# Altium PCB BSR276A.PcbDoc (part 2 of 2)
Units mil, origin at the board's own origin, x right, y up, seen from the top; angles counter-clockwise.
Board outline 2517.71 x 2251 mil, 4 copper layers (Top Layer, Signal Layer 1, Signal Layer 2, Bottom Layer), stack 61.6 mil thick; 70 components, 21 nets, 118 pads, 66 vias.
Unrouted connection lines stored in the file: 1.
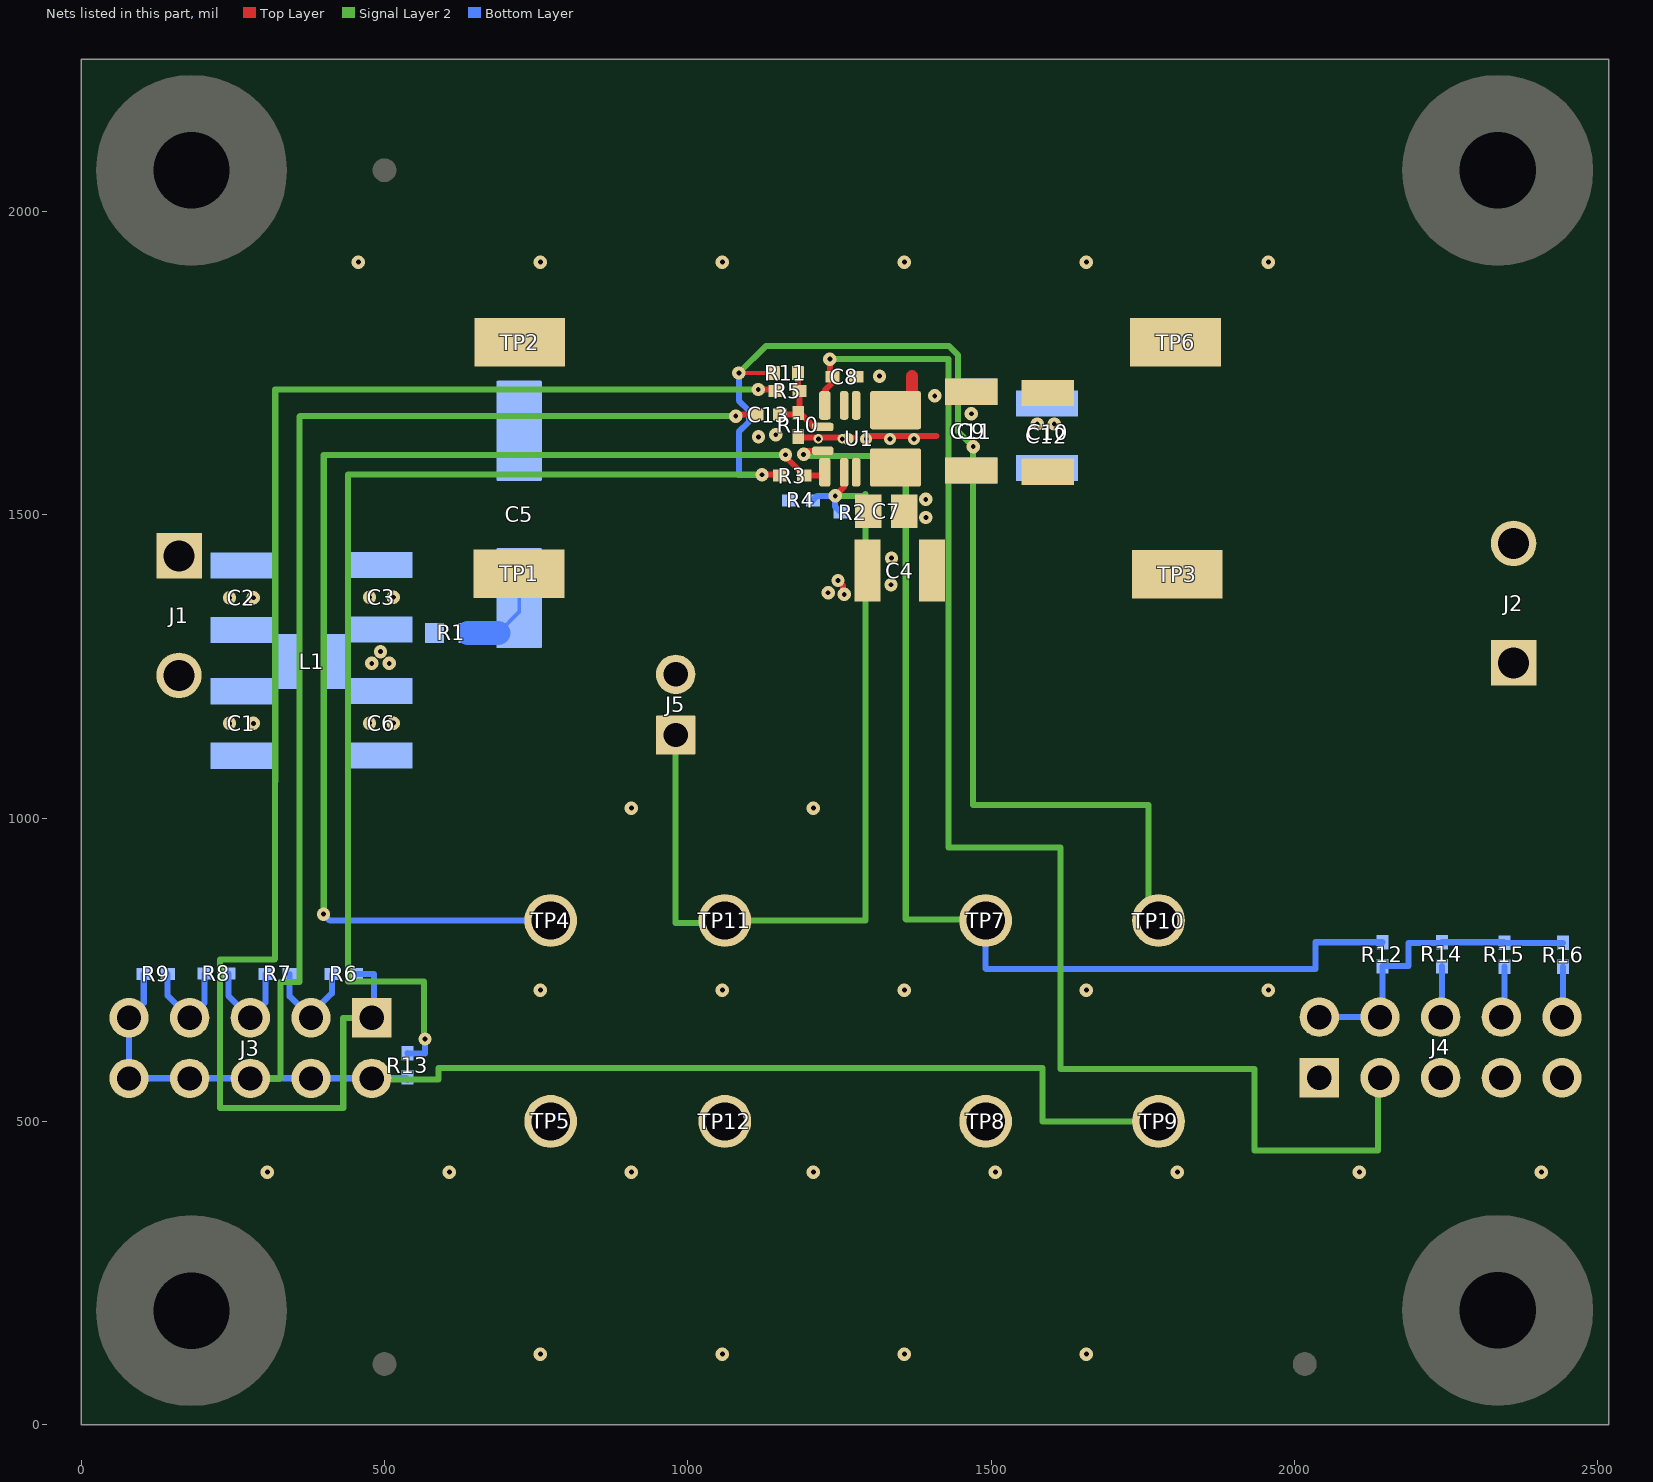
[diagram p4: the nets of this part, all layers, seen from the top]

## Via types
v1: diameter 22, hole 8, Top Layer to Bottom Layer, tented both sides, 61 vias
v2: diameter 19.68, hole 7.87, Top Layer to Bottom Layer, tented both sides, 3 vias
v3: diameter 15.75, hole 7.87, Top Layer to Bottom Layer, tented both sides, 2 vias

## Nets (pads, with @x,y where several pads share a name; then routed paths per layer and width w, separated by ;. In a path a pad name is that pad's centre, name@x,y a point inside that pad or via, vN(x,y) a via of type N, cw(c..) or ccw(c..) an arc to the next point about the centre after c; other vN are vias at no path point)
1.8Vout: J3.1 R5.1 R6.2 | length 2604.8
  Top Layer w10: v1(1116.14,1706.25) 1139.51,1706.25 1143.01,1702.76 1144.34,1704.09 R5.1@1144.69,1703.74
  Signal Layer 2 w10: J3.1@479,670.87 478.24,670.11 432.17,670.11 432.17,521.7 228.97,521.7 228.97,766.73 319,766.73 319.98,767.72 319.98,1060.04 320,1706.25 v1(1116.14,1706.25)
  Bottom Layer w10: R6.2@452.69,743.11 483.02,743.11 483.02,674.88 J3.1@479,670.87
2.5Vout: J3.3 R6.1 R7.2 | length 173.3
  Bottom Layer w10: R7.2@343.69,743.11 343.69,706.18 J3.3@379,670.87 379,676.65 413.32,710.96 R6.1@413.32,743.11
3.3Vout: J3.5 R7.1 R8.2 | length 171
  Bottom Layer w10: R8.2@242.69,744.09 242.69,707.18 J3.5@279,670.87 304.32,696.18 R7.1@304.32,743.11
5Vout: J3.7 R8.1 R9.2 | length 170.6
  Bottom Layer w10: R9.2@142.69,743.11 142.69,707.18 J3.7@179,670.87 203.32,695.18 R8.1@203.32,744.09
12Vout: C13.1 J3.2 J3.4 J3.6 J3.8 J3.9 J3.10 R9.1 R13.1 TP9.1 | length 3972.9
  Top Layer w10: v1(1079,1662.4) 1081.95,1665.35 C13.1@1112.8,1665.35
  Signal Layer 2 w10: J3.6@279,570.87 279.24,570.62 328.57,570.62 328.57,729.9 360,729.9 360,1661.4 361,1662.4 v1(1079,1662.4) ; J3.2@479,570.87 480.81,569.05 589.06,569.05 589.06,587.66 1584.92,587.66 1584.92,500 TP9.1@1776,500
  Bottom Layer w10: J3.10@79,570.87 J3.10@79,571.06 ; R9.1@103.32,743.11 103.32,695.18 J3.9@79,670.87 J3.10@79,571.06 ; R13.1@538.39,568.99 536.31,571.06 J3.10@79,571.06
GND: C1.2 C2.2 C3.2 C4.2 C5.1 C6.2 C7.2 C8.1 C9.2 C10.2 C11.2 C12.2 J1.1 J2.2 J4.1 J4.5 J4.7 J4.9 J5.2 R4.2 R10.1 TP2.1 TP5.1 TP6.1 TP8.1 TP12.1 U1.10 | length 207.7
  Top Layer w10: R10.1@1182.09,1628.36 1182.09,1626.89 U1.10@1272.64,1626.89 ; v2@1294,1629.69 1409.68,1629.69
  other v1: 757,116.39 1057,116.39 1357,116.39 1657,116.39 307,416.39 607,416.39 907,416.39 1207,416.39 1507,416.39 1807,416.39 2107,416.39 2407,416.39 757,716.39 1057,716.39 1357,716.39 1657,716.39 1957,716.39 907,1016.39 1207,1016.39 244.55,1156 283.92,1156 475.32,1156.38 514.68,1156.38 244.55,1363 283.92,1363 475.32,1364.01 514.68,1364.01 1334.92,1384.53 1335.84,1428.45 1392.41,1495.44 1392.25,1525.27 1116.64,1628.27 1145.12,1631.7 1576,1649.61 1604,1649.61 1467.52,1666.34 1407.21,1695.87 1315.95,1728.46 457,1916.39 757,1916.39 1057,1916.39 1357,1916.39 1657,1916.39 1957,1916.39
  other v2: 1294.09,1625 1333.46,1625 1372.83,1625
  other v3: 1215.35,1625 1254.72,1625
NetC5_2: C5.2 R1.1 | length 121.6
  Bottom Layer w6: C5.2@687.6,1305.13 722,1339.54 C5.2@722,1362.56
  Bottom Layer w40: R1.1@637.63,1305.13 C5.2@687.6,1305.13
NetJ4_2: J4.2 J4.4 R12.1 R14.2 R15.2 R16.2 | length 523.5
  Bottom Layer w10: J4.2@2041,671.85 J4.4@2141,671.85 2145,675.85 R12.1@2145,755.91 2188.03,755.91 2188.03,794.31 2242.03,794.31 R14.2@2243,795.28 2345.02,795.28 R15.2@2346,794.29 R16.2@2443,794.29 ; J4.4@2157.18,669.39 J4.4@2157.57,668.99
NetJ4_6: J4.6 R14.1 | length 91.4
  Bottom Layer w10: J4.6@2241,671.85 2243,673.85 R14.1@2243,755.91 ; J4.6@2254.92,671.65 2257.57,668.99 J4.6@2259.54,670.96
NetJ4_8: J4.8 R15.1 | length 85.1
  Bottom Layer w10: J4.8@2341,671.85 2346,676.85 R15.1@2346,754.92
NetJ4_10: J4.10 R16.1 | length 90.7
  Bottom Layer w10: J4.10@2441,671.85 2443,673.85 R16.1@2443,754.92 ; J4.10@2452.76,673.81 J4.10@2457.57,668.99
Vboot: U1.7
VCC: C8.2 J4.3 U1.8 | length 2409.2
  Top Layer w10: U1.8@1225.91,1680.12 1225.91,1704.83 1238.6,1717.52 C8.2@1238.6,1727.36 ; C8.2@1234.25,1733.27 v1(1234.25,1756.44)
  Signal Layer 2 w10: v1@1237.66,1759.84 v1(1234.25,1756.44) 1429.56,1756.44 1429.56,951.34 1614.61,951.34 1614.61,586.61 1934.41,586.61 1934.41,452.19 2137.61,452.19 2137.61,568.46 J4.3@2141,571.85
Ven: J5.1 R2.1 R4.1 TP11.1 U1.2 | length 1505.3
  Top Layer w10: v1@1245.57,1531 v1(1243,1531) 1257.87,1545.87 U1.2@1257.87,1569.88
  Signal Layer 2 w10: J5.1@980,1136.81 980,826.82 1056.82,826.82 TP11.1@1060.86,830.86 ; TP11.1@1061,831 TP11.1@1060.86,830.86 ; v1(1243,1531) 1289.86,1531 1293.31,1534.45 1293.31,830.86 TP11.1@1060.86,830.86
  Bottom Layer w10: TP11.1@1050.2,843.5 TP11.1@1054.82,838.88 ; R4.1@1206.31,1523.62 1213.69,1531 v1(1243,1531) 1243,1513.26 R2.1@1252.32,1503.94
Vfb: C13.2 R5.2 R10.2 R11.1 U1.9 | length 137.2
  Top Layer w6: R5.2@1181.42,1706.38 R5.2@1184.06,1703.74
  Top Layer w10: C13.2@1152.17,1664.86 1179.22,1664.86 R10.2@1182.09,1667.73 ; R5.2@1181.42,1706.38 R11.1@1181.42,1733.52 ; R5.2@1184.06,1703.74 1184.06,1669.7 R10.2@1182.09,1667.73 ; U1.9@1211.4,1645.75 1206.61,1645.75 1184.63,1667.73 R10.2@1182.09,1667.73
VIN: C3.1 C4.1 C6.1 C7.1 L1.2 R1.2 R2.2 TP1.1 U1.3 | length 27.3
  Top Layer w10: v1(1247.53,1391.55) 1255.58,1383.51 1255.58,1370.88 v1(1257.87,1368.59)
  other v1: 479,1254.92 507.87,1254.92 493.64,1274.33 1231.32,1371.26
VIN_EMI: C1.1 C2.1 J1.2 L1.1
VOUT: C9.1 C10.1 C11.1 C12.1 J2.1 R3.1 R11.2 R13.2 TP3.1 TP10.1 U1.4 | length 3723.9
  Top Layer w6: v1(1084.32,1733.52) R11.2@1142.05,1733.52
  Top Layer w10: v1(1122.32,1565.94) 1151.18,1565.94 R3.1@1152.56,1564.57
  Signal Layer 2 w10: v1(567,635.83) 565,637.83 565,730.33 440,730.33 440,1565.94 v1(1122.32,1565.94) ; v1(1084.32,1733.52) 1129.14,1778.34 1430.15,1778.34 1445.61,1762.88 1445.61,1637.06 v1(1470.47,1612.2) 1470.47,1021.16 1759.53,1021.16 1759.53,847.47 TP10.1@1776,831
  Bottom Layer w10: R13.2@538.39,612.3 538.46,612.22 567,612.22 v1(567,635.83) ; v1(1084.32,1733.52) 1084.32,1688.06 1100.91,1671.48 1100.91,1653.33 1084.32,1636.74 1084.32,1565.09 1121.46,1565.09 v1(1122.32,1565.94)
Vpgood: R3.2 TP4.1 U1.1 | length 1988.8
  Top Layer w10: v1(1161.1,1598.74) 1161.1,1595.4 R3.2@1191.93,1564.57 1220.59,1564.57 U1.1@1225.91,1569.88
  Signal Layer 2 w10: v1(399.54,841.54) 400,842 400,1598.74 v1(1161.1,1598.74)
  Bottom Layer w10: v1(399.54,841.54) 410.07,831 TP4.1@774,831 ; TP4.1@774.61,842.52 TP4.1@780.51,848.43
Vrt: R12.2 TP7.1 U1.11 | length 1876.4
  Top Layer w10: v1(1191.06,1599.49) 1196.89,1605.32 U1.11@1222.44,1605.32
  Signal Layer 2 w10: v1(1191.06,1599.49) 1193.62,1596.93 1359.35,1596.93 1359.35,833.33 1360,832.68 TP7.1@1491.14,832.68
  Bottom Layer w10: TP7.1@1491,831 1491,752.08 1492.05,751.03 2034.97,751.03 2034.97,795.28 R12.2@2145,795.28
Vsw: U1.5 U1.6 | length 78.4
  Top Layer w10: U1.5@1334.65,1680.12 U1.5@1342.52,1672.24 U1.5@1369.39,1699.12
  Top Layer w20: U1.5@1369.39,1699.12 1369.39,1728.35
pads on no net: FID1.1 FID2.1 FID3.1 H1.1 H2.1 H3.1 H4.1 SH-J1.0 SH-J2.0

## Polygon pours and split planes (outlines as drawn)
VIN on Signal Layer 2 "vin-mid1" (solid, pour order 48): 400,1355.41 400,1250.14 1273.59,1250.14 1273.59,1431.01 1210.21,1431.01 1210.21,1351.34
GND on Signal Layer 2 "gnd-mid2" (solid, pour order 58): -1219.49,-96.46 3730.51,-96.46 3730.51,3353.54 -1219.49,3353.54
GND on Top Layer "gnd-top" (solid, pour order 50): 1321.85,1458.92 1321.85,1363.12 1424.29,1363.12 1424.03,1363.37 1424.03,1458.92 1335.69,1458.92
VIN on Top Layer "vin-top-pin" (solid, pour order 60): 1262.82,1595.84 1262.82,1429.13 1321.85,1429.13 1321.11,1429.87 1321.11,1537.39 1292.91,1537.39 1288.89,1541.41 1289.74,1542.26 1289.74,1595.84
VIN on Top Layer "vin-top" (solid, pour order 39): 1211.85,1356.22 1321.85,1356.22 1321.85,1429.13 1211.85,1429.13
VIN on Top Layer "vin-top" (solid, pour order 46): 458.46,1236.26 590.09,1236.26 799.02,1236.26 799.02,1440.53 797,1442.56 647,1442.56 647,1304.86 458.46,1304.86
GND on Top Layer "gnd-top" (solid, pour order 59): 0,0 2517.69,0 2517.71,2250.99 0,2250.98
VOUT on Top Layer "vout-top" (solid, pour order 52): 1304.95,1615.32 1303.02,902.61 1305.92,905.51 2515,905.51 2515,1615.32
VIN on Bottom Layer "vin-bot" (solid, pour order 44): 395.37,1338.51 395.37,1182.54 546.27,1182.54 546.27,1239.14 590,1239.14 590,1338.51
GND on Bottom Layer "gnd-bot" (solid, pour order 56): 0,0 2517.68,0.03 2517.68,2251 0,2250.98
VIN_EMI on Bottom Layer "vin-emi-bot" (solid, pour order 42): 119,1298.23 119,1182.54 360,1182.54 360,1338.51 119,1338.51
VOUT on Bottom Layer "vout-bot" (solid, pour order 37): 1420,1633.62 1420,1549.46 1421.85,1551.31 1647.12,1551.31 1647.12,1605.02 1645,1607.13 1640.23,1602.36 1489,1602.36 1489,1632.87 1421,1632.87
VIN on Bottom Layer "vin-bot" (solid, pour order 38): 1276.6,1531 1276.44,1488.17 1278.01,1486.6 1275.67,1484.25 1244.76,1484.25 1244.76,1456.56 1244.76,1429.13 1221.08,1429.13 1247.53,1429.13 1247.53,1371.06 1321.11,1371.06 1321.11,1531
GND on Signal Layer 1 "gnd-mid1" (solid, pour order 54): 0,0 2517.69,0.02 2517.71,2250.97 0,2250.98

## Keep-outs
Keep-Out Layer:
  text ".Layer_Name" at 577,-858.49 h60

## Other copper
Top Layer:
  rectangle net Vsw: 1352.31,1713.54 1383.16,1741.1
  text ".Layer_Name" at 577,-858.49 h60
Bottom Layer:
  text ".Layer_Name" at 577,-858.49 h60

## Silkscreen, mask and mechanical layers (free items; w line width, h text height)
Top Overlay:
  lines w10: 1060.09,1742.13 1121.11,1742.13 ; 1062.26,1359.07 1123.28,1359.07 ; 1090,1360 1090,1741.14 ; 1129.46,1276.57 1129.46,1337.6 ; 1130,1310.04 1648.62,1310.04 ; 1649,1278.54 1649,1339.57
  text "'.PRJ_Number'.PCB_Rev" at 59,1740.16 h108.27
  text "10mm" at 1061,1481.78 h40 r90
  text "GND" at 341.54,1393 h60
  text "GND" at 1981.3,1393 h60
  text "13mm" at 1315.95,1254.92 h40
  text "VINEMI" at 350.39,1174 h60
  text "VOUT" at 1938.98,1174 h60
  text "2.2MHz" at 2049.1,802 h40 r90
  text "1MHz" at 2158.78,802 h40 r90
  text "800kHz" at 2265.75,802.17 h40 r90
  text "2.5VOUT" at 383.86,801.18 h40 r90
  text "300kHz" at 2473.26,800.2 h40 r90
  text "3.3VOUT" at 282.48,799.21 h40 r90
  text "1.8VOUT" at 507.87,799.21 h40 r90
  text "500kHz" at 2369.39,799.21 h40 r90
  text "5VOUT" at 182.54,796.26 h40 r90
  text "12VOUT" at 75.33,793.54 h40 r90
  text ".Layer_Name" at 577,-858.49 h60
Bottom Overlay:
  text ".Layer_Name" at 577,-858.49 h60
Top Paste:
  text ".Layer_Name" at 577,-858.49 h60
Bottom Paste:
  text ".Layer_Name" at 577,-858.49 h60
Top Solder:
  rectangle: 1352.31,1713.54 1383.16,1741.1
  text ".Layer_Name" at 577,-858.49 h60
  text ".Layer_Name" at 577,-858.49 h60
Bottom Solder:
  text ".Layer_Name" at 577,-858.49 h60
Drill Guide:
  text ".Layer_Name" at 577,-858.49 h60
M1 Board Outline:
  lines w10: 0,0 2517,0 2517,2250 0,2250 0,0
  text ".Layer_Name" at 577,-858.49 h60
M2 Board Dimensions:
  rectangle: 125,-400 500,-275
  rectangle: 0,-275 125,-150
  lines w7: 0,-275 1000,-275 ; 125,-400 125,-150 ; 250,-400 250,-150 ; 500,-400 500,-150 ; 750,-400 750,-150 ; 0,-400 0,-150 1000,-150 1000,-400 0,-400
  text ".Layer_Name" at 577,-858.49 h60
M3 3D STEP Top:
  text ".Layer_Name" at 577,-858.49 h60
M4 3D STEP Bottom:
  text ".Layer_Name" at 577,-858.49 h60
M5 Assembly Top:
  lines w10: -292,-930.17 6308,-930.17 ; -292,-726.83 6310,-726.83 ; -292,-523.5 -292,-1133.5 3713,-1133.5 6310,-1133.5 6310,-523.5 -291.5,-523.5 -291.5,-1133.5 1284,-1133.5 ; 2173,-1133.5 2173,-523.5 ; 3440,-726.83 3440,-523.5 ; 4280,-726.83 4280,-523.5 ; 4902,-1140 4902,-937.17
  text "COMPONENTS MARKED 'DNP' SHOULD NOT BE POPULATED." at 1153.5,-318.5 h60
  text "ASSEMBLY VARIANT:" at 1153,-434 h60
  text ".VariantName" at 2189,-434 h60
  text "PCB VIEWED FROM TOP SIDE" at -228.5,-655.67 h60
  text "BOARD #:" at 2248,-655.67 h60
  text ".PRJ_Number" at 2793.5,-655.67 h60
  text "REV:" at 3638,-655.67 h60
  text ".PCB_Rev" at 3929.5,-655.67 h60
  text "SVN REV:" at 4476,-655.67 h60
  text ".VersionControl_RevNumber" at 4982,-655.67 h60
  text "PLOT NAME =" at -228.5,-1064.34 h60
  text ".plot_File_Name" at 577,-1064.34 h60
  text "GENERATED    :" at 2250,-1064.34 h60
  text ".Print_Date" at 3119.5,-1064.34 h60
  text ".Print_Time" at 3848.5,-1064.34 h60
  text "TEXAS INSTRUMENTS" at 5113,-1064.34 h60
M6 Assembly Bottom:
  lines w10: -292.5,-727.33 6309.5,-727.33 ; -290.5,-930.67 6309.5,-930.67 ; 1115.5,-1140.5 1115.5,-937.67 ; 1737.5,-727.33 1737.5,-524 ; 2577.5,-727.33 2577.5,-524 ; 3844.5,-1134 3844.5,-524 ; 4733.5,-1134 6309,-1134 6309,-524 -292.5,-524 -292.5,-1134 2304.5,-1134 6309.5,-1134 6309.5,-524
  text "COMPONENTS MARKED 'DNP' SHOULD NOT BE POPULATED." at 6102,-318 h60
  text ".VariantName" at 5058,-434 h60
  text "ASSEMBLY VARIANT:" at 6097,-434 h60
  text ".VersionControl_RevNumber" at 1035.5,-656.17 h60
  text "SVN REV:" at 1541.5,-656.17 h60
  text ".PCB_Rev" at 2088,-656.17 h60
  text "REV:" at 2379.5,-656.17 h60
  text ".PRJ_Number" at 3224,-656.17 h60
  text "BOARD #:" at 3769.5,-656.17 h60
  text "PCB VIEWED FROM BOTTOM SIDE" at 6246,-656.17 h60
  text "TEXAS INSTRUMENTS" at 904.5,-1064.84 h60
  text ".Print_Time" at 2169,-1064.84 h60
  text ".Print_Date" at 2898,-1064.84 h60
  text "GENERATED    :" at 3767.5,-1064.84 h60
  text ".plot_File_Name" at 5440.5,-1064.84 h60
  text "PLOT NAME =" at 6246,-1064.84 h60
M9 Title Sheet:
  drawing of 56 lines, arcs and shapes, not listed
  text "1" at 1058.34,13381.39 h70
  text "2" at 4384,13381.39 h70
  text "3" at 7714,13381.39 h70
  text "4" at 11049,13381.39 h70
  text "5" at 14374,13381.39 h70
  text "6" at 17709,13381.39 h70
  text "A" at -463,11603.39 h70
  text "A" at 19237,11603.39 h70
  text "B" at -463,7853.39 h70
  text "B" at 19237,7853.39 h70
  text "C" at -463,4103.39 h70
  text "C" at 19237,4103.39 h70
  text "D" at -463,353.39 h70
  text "D" at 19237,353.39 h70
  text "PROJECT TITLE:" at 16143,268.39 h45
  text ".PRJ_Title" at 16193,135.06 h70
  text "DESIGNED FOR:" at 16143,-32.61 h45
  text ".PRJ_Customer" at 16193,-172.61 h70
  text "FILE NAME:" at 16143,-332.61 h45
  text ".PCB_File_Name_No_Path" at 16193,-452.61 h70
  text "Texas Instruments (TI) and/or its licensors do not warrant the accuracy or completeness of this specification" at 11173.5,-614.45 h45
  text "ENGINEER:" at 16143,-622.61 h45
  text "LAYOUT BY:" at 17648,-622.61 h45
  text "or any information contained therein. TI and/or its licensors do not warrant that this design will meet" at 11128.51,-727.11 h45
  text ".PRJ_Engineer" at 16193,-777.6 h70
  text ".PCB_Layout" at 17698.5,-777.6 h70
  text "the specifications, will be suitable for your application or fit for any particular purpose, or will operate in" at 11128.51,-839.78 h45
  text ".Layer_Name" at 577,-858.49 h60
  text "ALTIUM DESIGNER VERSION:" at 17648,-932.61 h45
  text "an implementation. TI and/or its licensors do not warrant that the design is production worthy. You should" at 11128.51,-952.44 h45
  text "completely validate and test your design implementation to confirm the system functionality for your application." at 11173.5,-1065.11 h45
  text ".print_Scale" at 16193,-1065.94 h70
  text ".Application_BuildNumber" at 17698.5,-1065.94 h70
  text "1" at 1058.34,-1318.61 h70
  text "2" at 4384,-1318.61 h70
  text "3" at 7714,-1318.61 h70
  text "4" at 11049,-1318.61 h70
  text "5" at 14374,-1318.61 h70
  text "6" at 17709,-1318.61 h70
M10 Fab Notes:
  drawing of 189 lines, arcs and shapes, not listed
  text "DESIGN INFORMATION" at 17178.02,6365.17 h60
  text "MIN. TRACK WIDTH:" at 16533.46,6233.05 h60
  text "8" at 17629.7,6233.05 h60
  text "MIL" at 17784.46,6233.05 h60
  text "MIN. CLEARANCE:" at 16533.46,6108.92 h60
  text "MIL" at 17784.46,6108.92 h60
  text "7.874" at 17459.65,6104.33 h60
  text "MIN. VIA PAD SIZE:" at 16533.46,5984.8 h60
  text "24" at 17599.71,5984.8 h60
  text "MIL" at 17784.46,5984.8 h60
  text "0.05mm (2MIL)" at 17228.46,5854.9 h60
  text "MINIMUM ANNULAR RING" at 16204.23,5846.67 h60
  text "EXTERNAL" at 17936.46,5846.67 h60
  text "PER" at 16404.23,5736.55 h60
  text "IPC-D-275 CLASS 2 LEVEL C" at 16624.23,5736.54 h60
  text "MIL, HOLES" at 18112.46,5636.07 h60
  text "+/-" at 17720,5627.48 h60
  text "+/-" at 18574,5627.48 h60
  text "REGISTRATION TOLERANCES:" at 16204.23,5626.42 h60
  text "METAL" at 17404,5626.42 h60
  text "5" at 17980.2,5626.42 h60
  text "3" at 18813.2,5626.42 h60
  text "MIL" at 18929.46,5626.42 h60
  text "HOLE SIZE TOLERANCE (UNLESS OTHERWISE SPECIFIED):" at 16204.23,5528.1 h60
  text "+/-" at 18574,5525.23 h60
  text "3" at 18813.2,5524.17 h60
  text "MIL" at 18929.46,5524.17 h60
  text "MATERIAL:" at 16129.46,5386.52 h60
  text "FR-4 High Tg" at 17115.9,5258 h60
  text "X" at 16971.46,5250.01 h60
  text "FR-408" at 16550.46,5245.49 h60
  text "OTHER" at 18038.46,5245.49 h60
  text "62 MIL (1.6mm) +/-10%" at 16870.56,5102.46 h60
  text "X" at 16750.46,5100.01 h60
  text "THICKNESS:" at 16204.23,5094.24 h60
  text "OTHER" at 18155.46,5094.24 h60
  text "TOLERANCE:" at 16204.23,4955.92 h60
  text "X" at 17052.46,4955.92 h60
  text "ANSI IPC-6012 TYPE 3 CLASS 2" at 17230.48,4955.92 h60
  text "OTHER +/-" at 17230.46,4811.73 h60
  text "BOW & TWIST:" at 16204.23,4666.54 h60
  text "X" at 17052.46,4666.54 h60
  text "ANSI IPC-6012 TYPE 3 CLASS 2" at 17230.48,4666.54 h60
  text "OTHER +/-" at 17230.46,4519.85 h60
  text "DRILLING:" at 16129.46,4389.23 h60
  text "NC_DRILL FILES" at 17890.46,4284.04 h60
  text "REFERENCE:" at 16204.23,4280.1 h60
  text "X" at 16861.46,4280.01 h60
  text "AS SHOWN" at 17039.46,4280.1 h60
  text "X" at 17762.46,4280.1 h60
  text "OTHER" at 18188.46,4137.85 h60
  text "PTH COPPER THICKNESS:" at 16203.91,4134.32 h60
  text "X" at 17343.14,4134.32 h60
  text "20-30 um" at 17471.14,4134.32 h60
  text "BOARD FINISH:" at 16129.46,3986.73 h60
  text "SILKSCREEN:" at 16284.68,3876.6 h60
  text "X" at 17242.46,3876.6 h60
  text "TOP" at 17359.46,3876.6 h60
  text "X" at 17752.46,3876.6 h60
  text "BOTTOM" at 17870.46,3876.6 h60
  text "SILKSCREEN COLOR:" at 16284.68,3721.41 h60
  text "X" at 17241.46,3721.41 h60
  text "WHITE" at 17359.46,3721.41 h60
  text "OTHER" at 17870.46,3721.41 h60
  text "X" at 17372.46,3577.96 h60
  text "GREEN" at 17490.46,3577.96 h60
  text "OTHER" at 18108.46,3577.96 h60
  text "SOLDER RESIST COLOR:" at 16284.68,3571.1 h60
  text "X" at 17372.46,3423.71 h60
  text "MATTE" at 17490.46,3423.71 h60
  text "SEMI-GLOSS" at 18108,3423.07 h60
  text "IMMERSION GOLD (ENIG)" at 17190.46,3250.94 h60
  text "ENEPIG" at 18528,3243.72 h60
  text "SURFACE FINISH:" at 16129.46,3242.72 h60
  text "X" at 17012.46,3242.72 h60
  text "IMM. TIN/SILVER OR EQUIV" at 16459,3105.4 h60
  text "OTHER" at 17890.46,3101.47 h60
  text "ARRAY/PANEL:" at 16129.46,2946.09 h60
  text "CUT AND TRIM PER M1 BOARD OUTLINE" at 17190.46,2937.87 h60
  text "N.C. ROUTE" at 17190.46,2801.9 h60
  text "X" at 17878.46,2801.9 h60
  text "V. SCORE" at 18056.46,2801.9 h60
  text "CERTIFICATION:" at 16129.46,2672.77 h60
  text "MATERIALS AND WORKMANSHIP FOR ALL PCBS" at 16854.46,2672.77 h60
  text "TO MEET OR EXCEED THE REQUIREMENTS OF:" at 16854.46,2578.71 h60
  text "X" at 16491.97,2450.08 h60
  text "ANSI IPC-A-600F CLASS ->" at 16619.96,2450.08 h60
  text "X" at 18267.97,2450.08 h60
  text "2" at 18377.96,2450.08 h60
  text "1" at 18062.96,2448.58 h60
  text "3" at 18731.96,2448.58 h60
  text "X" at 17303.97,2302.39 h60
  text "RoHS" at 17431.96,2302.39 h60
  text "OTHER" at 18076.36,2302.39 h60
  text "PER ORDER" at 18473.42,2302.39 h60
  text "ALL BOARDS MUST MEET OR EXCEED UL94-V0 REQUIREMENTS." at 16157,2148.57 h60
  text "PCB MUST BEAR THE UL94V-0 UL REGISTERED MATERIAL ID NUMBER" at 16157,2032.5 h60
  text "ADDITIONAL REQUIREMENTS:" at 16129.46,1863.08 h60
  text "MICROSECTION:" at 16204.23,1755.95 h60
  text "YES" at 17109.96,1755.95 h60
  text "REQUIRED" at 17971.46,1611.62 h60
  text "BARE BOARD ELEC. TEST:" at 16204.23,1608.76 h60
  text "NONE" at 17509.96,1608.76 h60
  text "X" at 17853.46,1608.76 h60
  text "PER ORDER" at 18563.46,1608.76 h60
  text "XX MIL VIAS REQUIRE NON-CONDUCTIVE FILL AND PLANARIZE" at 16372.38,1403.82 h59
  text "XX MIL VIAS REQUIRE CONDUCTIVE FILL AND PLANARIZE" at 16380.38,1299.84 h60
  text "OUTER XX MIL TRACES REQUIRE 50 OHM SINGLE-ENDED IMPEDANCE" at 16379.39,1136.46 h58
  text "LAYER 2 & 3 (INNER LAYERS) XX MIL WIDE, XX MIL SPACE / TRACES REQUIRE 100 OHM DIFFERENTIAL IMPEDANCE" at 16371.39,900.74 h60
  text ".Layer_Name" at 577,-858.49 h60
M11 Gerber Information:
  lines w10: -292,-930.17 6308,-930.17 ; -292,-726.83 6310,-726.83 ; -292,-523.5 -292,-1133.5 3713,-1133.5 6310,-1133.5 6310,-523.5 -291.5,-523.5 -291.5,-1133.5 1284,-1133.5 ; 2173,-1133.5 2173,-523.5 ; 3440,-726.83 3440,-523.5 ; 4280,-726.83 4280,-523.5 ; 4902,-1140 4902,-937.17
  text "ALL ARTWORK VIEWED FROM TOP SIDE" at -228.5,-655.67 h60
  text "BOARD #:" at 2248,-655.67 h60
  text ".PRJ_Number" at 2793.5,-655.67 h60
  text "REV:" at 3638,-655.67 h60
  text ".PCB_Rev" at 3929.5,-655.67 h60
  text "SVN REV:" at 4476,-655.67 h60
  text ".VersionControl_RevNumber" at 4982,-655.67 h60
  text "LAYER NAME =" at -228.5,-858.49 h60
  text "PLOT NAME =" at -228.5,-1064.34 h60
  text ".plot_File_Name" at 577,-1064.34 h60
  text "GENERATED    :" at 2250,-1064.34 h60
  text ".Print_Date" at 3119.5,-1064.34 h60
  text ".Print_Time" at 3848.5,-1064.34 h60
  text "TEXAS INSTRUMENTS" at 5113,-1064.34 h60
M12 Stackup:
  drawing of 1212 lines, arcs and shapes, not listed
  text "Layer" at 9998.2,13002.68 h60
  text "Name" at 10408.11,13002.68 h60
  text "Material" at 11347.85,13002.68 h60
  text "Thickness" at 12207.62,13002.68 h60
  text "Constant" at 12857.46,13002.68 h60
  text "Board Layer Stack" at 13427.32,13002.68 h60
  text "Board Layer Stack" at 14547,13002.68 h60
  text "Board Layer Stack" at 15666.68,13002.68 h60
  text "Board Layer Stack" at 16786.37,13002.68 h60
  text "Board Layer Stack" at 17906.05,13002.68 h60
  text "Top Overlay" at 10408.11,12882.68 h60
  text "Top Solder" at 10408.11,12762.68 h60
  text "Solder Resist" at 11347.85,12762.68 h60
  text "0.40mil" at 12207.62,12762.68 h60
  text "3.5" at 12857.46,12762.68 h60
  text "1" at 9998.2,12642.68 h60
  text "Top Layer" at 10408.11,12642.68 h60
  text "1.40mil" at 12207.62,12642.68 h60
  text "Dielectric 1" at 10408.11,12522.68 h60
  text "FR-4 High Tg" at 11347.85,12522.68 h60
  text "8.00mil" at 12207.62,12522.68 h60
  text "4.2" at 12857.46,12522.68 h60
  text "2" at 9998.2,12402.68 h60
  text "Signal Layer 1" at 10408.11,12402.68 h60
  text "1.40mil" at 12207.62,12402.68 h60
  text "Dielectric 2" at 10408.11,12282.68 h60
  text "FR-4 High Tg" at 11347.85,12282.68 h60
  text "40.00mil" at 12207.62,12282.68 h60
  text "4.2" at 12857.46,12282.68 h60
  text "3" at 9998.2,12162.68 h60
  text "Signal Layer 2" at 10408.11,12162.68 h60
  text "1.40mil" at 12207.62,12162.68 h60
  text "Dielectric 3" at 10408.11,12042.68 h60
  text "FR-4 High Tg" at 11347.85,12042.68 h60
  text "8.00mil" at 12207.62,12042.68 h60
  text "4.2" at 12857.46,12042.68 h60
  text "4" at 9998.2,11922.68 h60
  text "Bottom Layer" at 10408.11,11922.68 h60
  text "1.40mil" at 12207.62,11922.68 h60
  text "Bottom Solder" at 10408.11,11802.68 h60
  text "Solder Resist" at 11347.85,11802.68 h60
  text "0.40mil" at 12207.62,11802.68 h60
  text "3.5" at 12857.46,11802.68 h60
  text "Bottom Overlay" at 10408.11,11682.68 h60
  text ".Layer_Name" at 577,-858.49 h60
M13 Component Bodies Top:
  text ".Layer_Name" at 577,-858.49 h60
M14 Component Bodies Bottom:
  text ".Layer_Name" at 577,-858.49 h60
M15 Courtyards Top:
  text ".Layer_Name" at 577,-858.49 h60
M16 Courtyards Bottom:
  text ".Layer_Name" at 577,-858.49 h60
Drill Drawing:
  circle w10: c5443.72,2662.68 r27.63
  lines w10: 5416.09,2814.63 5471.34,2814.63 5443.72,2759.38 5416.09,2814.63 ; 5416.09,2883.7 5471.34,2883.7 5471.34,2938.95 5416.09,2938.95 5416.09,2883.7 ; 5416.09,3021.83 5429.9,3021.83 5443.72,3008.02 5457.53,3021.83 5471.34,3021.83 5457.53,3035.64 5471.34,3049.46 5457.53,3049.46 5443.72,3063.27 5429.9,3049.46 5416.09,3049.46 5429.9,3035.64 5416.09,3021.83 ; 5416.09,3146.15 5429.9,3146.15 5429.9,3132.34 5457.53,3132.34 5457.53,3146.15 5471.34,3146.15 5471.34,3173.78 5457.53,3173.78 5457.53,3187.59 5429.9,3187.59 5429.9,3173.78 5416.09,3173.78 5416.09,3146.15 ; 5416.09,3256.66 5443.72,3270.47 5471.34,3256.66 5457.53,3284.28 5471.34,3311.91 5443.72,3298.1 5416.09,3311.91 5429.9,3284.28 5416.09,3256.66
  lines w12: 5366,2597.76 8597.49,2597.76 ; 5366,3343.68 8597.49,3343.68 ; 5703.86,2473.44 5703.86,3468 ; 6035.86,2473.44 6035.86,3468 ; 6672.43,2473.44 6672.43,3468 ; 6931.57,2473.44 6931.57,3468 ; 7306.72,2473.44 7306.72,3468 ; 8031.05,2473.44 8031.05,3468 ; 5366,2473.44 8597.49,2473.44 8597.49,3468 5366,3468 5366,2473.44
  text "Symbol" at 5440.59,3380.98 h72
  text "Quantity" at 5741.16,3380.98 h72
  text "Finished Hole Size" at 6073.16,3380.98 h72
  text "Plated" at 6709.72,3380.98 h72
  text "Hole Type" at 6968.86,3380.98 h72
  text "Drill Layer Pair" at 7344.02,3380.98 h72
  text "Hole Tolerance" at 8068.35,3380.98 h72
  text "5" at 5741.16,3256.66 h60
  text "7.87mil (0.200mm)" at 6073.16,3256.66 h60
  text "PTH" at 6709.72,3256.66 h60
  text "Round" at 6968.86,3256.66 h60
  text "Top Layer - Bottom Layer" at 7344.02,3256.66 h60
  text "61" at 5741.16,3132.34 h60
  text "8.00mil (0.203mm)" at 6073.16,3132.34 h60
  text "PTH" at 6709.72,3132.34 h60
  text "Round" at 6968.86,3132.34 h60
  text "Top Layer - Bottom Layer" at 7344.02,3132.34 h60
  text "22" at 5741.16,3008.02 h60
  text "40.00mil (1.016mm)" at 6073.16,3008.02 h60
  text "PTH" at 6709.72,3008.02 h60
  text "Round" at 6968.86,3008.02 h60
  text "Top Layer - Bottom Layer" at 7344.02,3008.02 h60
  text "4" at 5741.16,2883.7 h60
  text "51.18mil (1.300mm)" at 6073.16,2883.7 h60
  text "PTH" at 6709.72,2883.7 h60
  text "Round" at 6968.86,2883.7 h60
  text "Top Layer - Bottom Layer" at 7344.02,2883.7 h60
  text "8" at 5741.16,2759.38 h60
  text "63.00mil (1.600mm)" at 6073.16,2759.38 h60
  text "PTH" at 6709.72,2759.38 h60
  text "Round" at 6968.86,2759.38 h60
  text "Top Layer - Bottom Layer" at 7344.02,2759.38 h60
  text "4" at 5741.16,2635.06 h60
  text "125.98mil (3.200mm)" at 6073.16,2635.06 h60
  text "PTH" at 6709.72,2635.06 h60
  text "Round" at 6968.86,2635.06 h60
  text "Top Layer - Bottom Layer" at 7344.02,2635.06 h60
  text "104 Total" at 5741.16,2510.74 h60
  text ".Layer_Name" at 577,-858.49 h60
M17 Embedded Cavity:
  text ".Layer_Name" at 577,-858.49 h60
M18 Embedded Assembly:
  text ".Layer_Name" at 577,-858.49 h60
M19 Embedded Keepout:
  text ".Layer_Name" at 567,-858.49 h60

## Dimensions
0,-400 to 1000,-400 on M2 Board Dimensions
0,0 to 2517.71,0 on M2 Board Dimensions
0,0 to 2517.69,2250.98 on M2 Board Dimensions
